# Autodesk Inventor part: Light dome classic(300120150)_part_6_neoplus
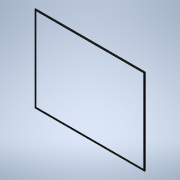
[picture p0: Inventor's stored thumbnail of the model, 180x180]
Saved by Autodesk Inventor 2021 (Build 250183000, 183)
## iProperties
Created: 2026-04
Part Number: Light dome classic(300120150)_part_6_neoplus
Material: Generic
Catalog Web Link: www.3dfindit.com
Description: Light dome classic_part_6_neoplus-
Vendor: KINGSPAN
Document SubType Name: Modeling
Designer: psAdmin
Manufacturer: KINGSPAN
Mass: 938.483 g
Surface Area: 2597.89 cm^2
Volume: 938.483 cm^3
Density: 1 g/cm^3
Appearance: PSOLRGB-128-128-128
Category: PARTsolutions
Company: KINGSPAN
Title: Light dome classic(300120150)_part_6_neoplus
Author: Cadenas PARTsolutions
PSOL_IDENT_0: {$CADENAS_DATA/23d-libs/kingspan_kla/light_dome_classic_neoplus/parts/part_6.prj},268 {VTYP=3D},{NB=
PSOL_IDENT_1: Light dome classic(300120150)_part_6_neoplus},{LINA=Light dome classic(300120150)_part_6_neoplus},{N
PSOL_IDENT_2: N=Light dome classic_part_6_neoplus},{DATE=20.03.2025 09:30:52},{GEOMDATE=27.10.2022 10:10:00},{VERS
PSOL_IDENT_3: ION=},{LINEID=10},{WBVAR=LODLEVEL,L,W},{WBNUMERIC=W}  {NB=Light dome classic(300120150)_part_6_neopl
PSOL_IDENT_4: us},{LINA=Light dome classic(300120150)_part_6_neoplus},{KT=DUMMY},{IDNR=},{PN=Light dome classic},{
PSOL_IDENT_5: LODLEVEL=300},{L=120},{W=150},{WX=120,150,180,240,270,300},{LX=1200},{XWX=1500}
NB: Light dome classic(300120150)_part_6_neoplus
NN: Light dome classic_part_6_neoplus
NBSYN: $PN.($LODLEVEL.$L.$W.)_part_6_neoplus
LINA: Light dome classic(300120150)_part_6_neoplus
CATALOG: Light + Air
PN: Light dome classic
LODLEVEL: 300
L: 120
W: 150
SUPPLIER: KINGSPAN
ARTICLENO: Light dome classic(300120150)_part_6_neoplus
BOMINFO: Light dome classic(300120150)_part_6_neoplus
CREATOR: CADENAS GmbH
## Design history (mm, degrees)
sketch "Sketch_1"
  geometry: L1 (-673.235, 17.946)-(-683.911, 17.946); L2 (-685.365, 1.946)-(-676.535, 1.946); L3 (-674.735, 12.349)-(-673.235, 17.946); A1 r 12.5 centre (-675.1, 9.079) between (-683.911, 17.946) and (-685.365, 1.946); A2 r 12.5 centre (-686.8, 9.079) between (-676.535, 1.946) and (-674.735, 12.349)
  constraints: 6 end point, 4 point on circle, 2 centre point
extrude "Extrusion1" join sketch "Sketch_1" stored distance "d0" = 2400; taper "d1" = 0 deg
sketch "Sketch_2"
  geometry: L1 (523.235, 17.946)-(524.735, 12.349); L2 (526.535, 1.946)-(535.365, 1.946); L3 (533.911, 17.946)-(523.235, 17.946); A1 r 12.5 centre (536.8, 9.079) between (524.735, 12.349) and (526.535, 1.946); A2 r 12.5 centre (525.1, 9.079) between (535.365, 1.946) and (533.911, 17.946)
  constraints: 6 end point, 4 point on circle, 2 centre point
extrude "Extrusion2" join sketch "Sketch_2" stored distance "d2" = 3000; taper "d3" = 0 deg
sketch "Sketch_3"
  geometry: L1 (683.911, 17.946)-(673.235, 17.946); L2 (673.235, 17.946)-(674.735, 12.349); L3 (676.535, 1.946)-(685.365, 1.946); A1 r 12.5 centre (675.1, 9.079) between (685.365, 1.946) and (683.911, 17.946); A2 r 12.5 centre (686.8, 9.079) between (674.735, 12.349) and (676.535, 1.946)
  constraints: 6 end point, 4 point on circle, 2 centre point
extrude "Extrusion3" join sketch "Sketch_3" stored distance "d4" = 2400; taper "d5" = 0 deg
sketch "Sketch_4"
  geometry: L1 (-523.235, 17.946)-(-533.911, 17.946); L2 (-535.365, 1.946)-(-526.535, 1.946); L3 (-524.735, 12.349)-(-523.235, 17.946); A1 r 12.5 centre (-525.1, 9.079) between (-533.911, 17.946) and (-535.365, 1.946); A2 r 12.5 centre (-536.8, 9.079) between (-526.535, 1.946) and (-524.735, 12.349)
  constraints: 6 end point, 4 point on circle, 2 centre point
extrude "Extrusion4" join sketch "Sketch_4" stored distance "d6" = 3000; taper "d7" = 0 deg
sketch "Sketch_5"
  geometry: L1 (-679.25, 37.946)-(-1500, 37.946); L2 (-1500, 37.946)-(-1500, -12.054); L3 (-1500, -12.054)-(-686.988, -12.054); L4 (-686.988, -12.054)-(-686.988, 5.216); L5 (-683.911, 17.946)-(-679.25, 17.946); L6 (-679.25, 17.946)-(-679.25, 37.946); A1 r 12.5 centre (-675.1, 9.079) between (-683.911, 17.946) and (-686.988, 5.216)
  constraints: 12 end point, 2 point on circle, 1 centre point
extrude "Extrusion5" cut sketch "Sketch_5" stored distance "d8" = 3000; taper "d9" = 0 deg
sketch "Sketch_6"
  geometry: L1 (1500, -12.054)-(1500, 37.946); L2 (1500, 37.946)-(679.25, 37.946); L3 (679.25, 37.946)-(679.25, 17.946); L4 (679.25, 17.946)-(683.911, 17.946); L5 (686.988, 5.216)-(686.988, -12.054); L6 (686.988, -12.054)-(1500, -12.054); A1 r 12.5 centre (675.1, 9.079) between (686.988, 5.216) and (683.911, 17.946)
  constraints: 12 end point, 2 point on circle, 1 centre point
extrude "Extrusion6" cut sketch "Sketch_6" stored distance "d10" = 3000; taper "d11" = 0 deg
sketch "Sketch_7"
  geometry: L1 (529.25, 37.946)-(529.25, 17.946); L2 (529.25, 17.946)-(533.911, 17.946); L3 (536.988, 5.216)-(536.988, -12.054); L4 (536.988, -12.054)-(1500, -12.054); L5 (1500, -12.054)-(1500, 37.946); L6 (1500, 37.946)-(529.25, 37.946); A1 r 12.5 centre (525.1, 9.079) between (536.988, 5.216) and (533.911, 17.946)
  constraints: 12 end point, 2 point on circle, 1 centre point
extrude "Extrusion7" cut sketch "Sketch_7" stored distance "d12" = 3000; taper "d13" = 0 deg
sketch "Sketch_8"
  geometry: L1 (-529.25, 37.946)-(-1500, 37.946); L2 (-1500, 37.946)-(-1500, -12.054); L3 (-1500, -12.054)-(-536.988, -12.054); L4 (-536.988, -12.054)-(-536.988, 5.216); L5 (-533.911, 17.946)-(-529.25, 17.946); L6 (-529.25, 17.946)-(-529.25, 37.946); A1 r 12.5 centre (-525.1, 9.079) between (-533.911, 17.946) and (-536.988, 5.216)
  constraints: 12 end point, 2 point on circle, 1 centre point
extrude "Extrusion8" cut sketch "Sketch_8" stored distance "d14" = 3000; taper "d15" = 0 deg
sketch "Sketch_10"
  geometry: L1 (-680.95, -7.054)-(-680.95, -1.143); L2 (-687.201, 5.946)-(-693.235, 5.946); L3 (-693.235, 5.946)-(-693.235, -7.054); L4 (-693.235, -7.054)-(-680.95, -7.054); A1 r 3.851 centre (-680.95, 2.708) between (-683.505, -0.173) and (-680.95, -1.143); A2 r 12.5 centre (-675.1, 9.079) between (-687.201, 5.946) and (-683.505, -0.173)
  constraints: 8 end point, 4 point on circle, 2 centre point
extrude "Extrusion9" cut sketch "Sketch_10" stored distance "d16" = 1200; taper "d17" = 0 deg
sketch "Sketch_11"
  geometry: L1 (543.235, 5.946)-(537.201, 5.946); L2 (530.95, -1.143)-(530.95, -7.054); L3 (530.95, -7.054)-(543.235, -7.054); L4 (543.235, -7.054)-(543.235, 5.946); A1 r 12.5 centre (525.1, 9.079) between (533.505, -0.173) and (537.201, 5.946); A2 r 3.851 centre (530.95, 2.708) between (530.95, -1.143) and (533.505, -0.173)
  constraints: 8 end point, 4 point on circle, 2 centre point
extrude "Extrusion10" cut sketch "Sketch_11" stored distance "d18" = 1500; taper "d19" = 0 deg
sketch "Sketch_12"
  geometry: L1 (693.235, 5.946)-(687.201, 5.946); L2 (680.95, -1.143)-(680.95, -7.054); L3 (680.95, -7.054)-(693.235, -7.054); L4 (693.235, -7.054)-(693.235, 5.946); A1 r 12.5 centre (675.1, 9.079) between (683.505, -0.173) and (687.201, 5.946); A2 r 3.851 centre (680.95, 2.708) between (680.95, -1.143) and (683.505, -0.173)
  constraints: 8 end point, 4 point on circle, 2 centre point
extrude "Extrusion11" cut sketch "Sketch_12" stored distance "d20" = 1200; taper "d21" = 0 deg
sketch "Sketch_13"
  geometry: L1 (-543.235, 5.946)-(-543.235, -7.054); L2 (-543.235, -7.054)-(-530.95, -7.054); L3 (-530.95, -7.054)-(-530.95, -1.143); L4 (-537.201, 5.946)-(-543.235, 5.946); A1 r 3.851 centre (-530.95, 2.708) between (-533.505, -0.173) and (-530.95, -1.143); A2 r 12.5 centre (-525.1, 9.079) between (-537.201, 5.946) and (-533.505, -0.173)
  constraints: 8 end point, 4 point on circle, 2 centre point
extrude "Extrusion12" cut sketch "Sketch_13" stored distance "d22" = 1500; taper "d23" = 0 deg
node "IP_6_XY"
node "IP_6_YZ"
node "IP_6_ZX"
node "IP_6_X"
node "IP_6_Y"
node "IP_6_Z"
node "IP_6_Center"
body "Solid1"
other parameters: "d24" = 0
